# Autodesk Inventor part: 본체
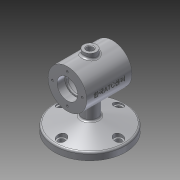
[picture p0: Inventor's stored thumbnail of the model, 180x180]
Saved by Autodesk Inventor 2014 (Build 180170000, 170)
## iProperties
Created: 2018-12
Part Number: 본체
Material: 알루미늄 6061
Document SubType Name: Modeling
Designer: oa-51
Density: 2.71 g/cm^3
Appearance: 알루미늄 - 평지
Mass: 687.765 g
Surface Area: 556.058 cm^2
Volume: 253.788 cm^3
Author: oa-51
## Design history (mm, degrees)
sketch "스케치1"
  geometry: C1 r 55 at (0, 0); 1 further point
  constraints: 1 centre point, 1 coincident
  dimensions: "d0" = 110 diameter of C1
extrude "돌출1" new body sketch "스케치1" distance "d1" = 11; taper "d2" = 0 deg
sketch "스케치2"
  geometry: L1 (55, 0)-(55, 11) reference; L2 (-55, 0)-(-55, 11) reference; L3 (-55, 11)-(0, 25.737); L4 (55, 11)-(0, 25.737); L5 (55, 11)-(-55, 11) reference; L6 (0, 25.737)-(0, 11); L7 (-55, 11)-(0, 11); 1 further point
  constraints: 8 end point, 1 collinear, 1 midpoint
  dimensions: "d4" = 75 deg angle of L4 L1; "d5" = 75 deg angle of L3 L2
revolve "회전1" sketch "스케치2" stored, may be unused: angle "d6" = 90 deg
sketch "스케치4"
  geometry: L1 (-46.167, 75)-(46.167, 75); L2 (-35, 75)-(-35, 105); L3 (-35, 105)-(35, 105); L4 (35, 105)-(35, 75); 3 further points
  constraints: 8 end point, 3 perpendicular, 2 midpoint, 2 point on line, 2 vertical alignment, 1 horizontal
  dimensions: "d7" = 75 distance from line of L1 point (0, 0); "d8" = 60 diameter of L3 L1; "d9" = 70 distance of L2.end L3.end
revolve "회전2" sketch "스케치4" stored, may be unused: angle "d10" = 90 deg
sketch "스케치5" dims "d11" = 46
  geometry: C1 r 30 at (0, 0) reference; 6 further points
  constraints: 2 vertical alignment, 1 coincident, 7 other
  dimensions: "d14" = 360 deg dimension on C1.centre point (0, 23) (derived)
hole "구멍1" sketch "스케치5" at (0, 23), (-23, 0), (0, -23), (23, 0) diameter "d16" = 3.242; stored, may be unused: countersink angle "d20" = 90 deg, drill point angle "d22" = 118 deg; dims "d17" = 8, "d18" = 4, "d19" = 2, "d21" = 10
sketch "스케치6"
  geometry: L1 (-35, 45)-(-35, 105) reference; L2 (35, 45)-(35, 105) reference; L3 (-35, 75)-(35, 75); L4 (-35, 91)-(-23, 91); L5 (-23, 91)-(-23, 89); L6 (-23, 89)-(-20, 89); L7 (-20, 89)-(-20, 100); L8 (-20, 100)-(20, 100); L9 (20, 100)-(20, 89); L10 (20, 89)-(23, 89); L11 (23, 89)-(23, 91); L12 (23, 91)-(35, 91); L13 (-35, 91)-(-35, 75); L14 (35, 91)-(35, 75); 2 further points
  constraints: 24 end point, 7 parallel, 5 collinear, 3 midpoint, 2 perpendicular, 2 point on line, 1 horizontal, 1 vertical alignment
  dimensions: "d23" = 32 diameter of L4 L3; "d24" = 28 diameter of L6 L3; "d25" = 50 diameter of L8 L3; "d26" = 12 distance of L4.start L4.end; "d27" = 40 distance of L7.end L8.end
revolve "회전3" sketch "스케치6" stored, may be unused: angle "d28" = 90 deg
fillet "모깎기1" dims "d29" = 3, "d30" = 0.3
node "작업 평면2"
sketch "스케치7"
  geometry: C1 r 10 at (0, 0); 1 further point
  constraints: 1 centre point, 1 coincident
  dimensions: "d32" = 20 diameter of C1
extrude "돌출2" join sketch "스케치7" stored distance "d33" = 10; taper "d34" = 0 deg
sketch "스케치8"
  geometry: C1 r 10 at (0, 0) reference; C2 r 5 at (0, 0)
  constraints: 1 centre point, 1 coincident
  dimensions: "d35" = 10 diameter of C2
extrude "돌출3" cut sketch "스케치8" stored distance "d36" = 10; taper "d37" = 0 deg
chamfer "모따기1" distance "d38" = 1; stored, may be unused: second distance "d39" = 2, angle "d40" = 45 deg
chamfer "모따기2" distance "d41" = 1; stored, may be unused: second distance "d42" = 2, angle "d43" = 45 deg
node "작업 평면3"
sketch "스케치9"
  geometry: C1 r 12 at (0, 0); 1 further point
  constraints: 1 centre point, 1 coincident
  dimensions: "d45" = 24 diameter of C1
extrude "돌출4" join sketch "스케치9" stored distance "d46" = 10; taper "d47" = 0 deg
sketch "스케치10" dims "d48" = 88
  geometry: 6 further points
  constraints: 2 vertical alignment, 1 coincident, 7 other
  dimensions: "d51" = 360 deg dimension on point (0, 0) point (0, 44) (derived)
sketch "스케치11" dims "d53" = 88
  geometry: C1 r 55 at (0, 0) reference; 5 further points
  constraints: 2 horizontal alignment, 1 coincident, 7 other
  dimensions: "d56" = 360 deg dimension on C1.centre point (44, 0) (derived)
hole "구멍2" sketch "스케치11" at (-44, 0), (0, 44), (0, -44), (44, 0) diameter "d58" = 9; stored, may be unused: countersink angle "d62" = 90 deg, drill point angle "d64" = 0 deg; dims "d59" = 8, "d60" = 14, "d61" = 2, "d63" = 10
hole "구멍3" sketch "스케치10" diameter "d65" = 14; stored, may be unused: countersink angle "d69" = 90 deg, drill point angle "d71" = 0 deg; dims "d66" = 8, "d67" = 14, "d68" = 2, "d70" = 8
fillet "모깎기2" dims "d72" = 3
node "작업 평면4"
sketch "스케치12"
  geometry: L1 (-35, 30)-(35, 30) reference; 2 further points
  constraints: 1 vertical alignment, 1 other
  dimensions: "d73" = 30 distance from line of point (0, 0) L1
feature "엠보싱1" sketch "스케치12" dims "d74" = 0.5, "d75" = 0
node "솔리드1"
mirror "대칭1"
node "작업 평면1"
other parameters: "d31" = -112, "d44" = -18
